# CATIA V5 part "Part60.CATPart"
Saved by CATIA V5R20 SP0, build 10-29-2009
Part number: FA 042200-3
Revision: ANY
Definition: UNKNOWN
Nomenclature: FA 042200-3
Source: Unknown
Bounding box of the stored display mesh (mm): x 0 to 2, y -1.45 to 1.45, z -1.45 to 1.45
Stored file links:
  C:\Users\Utente\Desktop\IO LAVORO\3D X SITO CF\CUMSA\3D files FA\FA 042212-20\Part60.CATPart

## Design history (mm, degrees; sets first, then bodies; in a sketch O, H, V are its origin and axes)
Body1 "Revolución1" (main body)
  Solid1: solid without history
